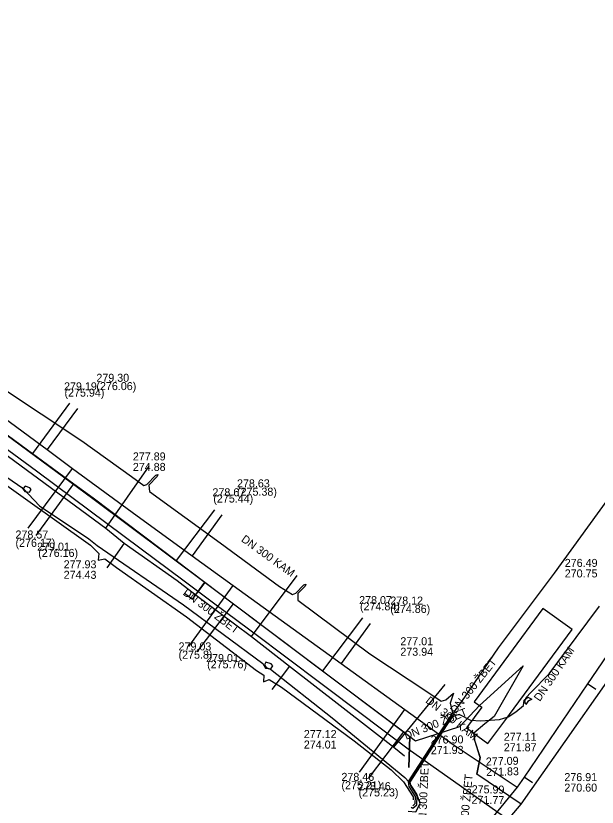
# Model space of a CAD drawing. Extents: x -598233 to -596890, y -1157848 to -1156431.
# Drawn here: x -597596.8 to -597538.8, y -1156886.7 to -1156807.7 of the extents above; entities that cross this region are included whole.
import ezdxf

# ---------------------------------------------------------------- set-up
doc = ezdxf.new("R2010")
doc.units = 0
for name, color, linetype in [('Vrstva 1', 7, 'Continuous'), ('Vrstva 13', 7, 'Continuous'), ('Vrstva 19', 7, 'Continuous'), ('Vrstva 3', 7, 'Continuous'), ('Vrstva 4', 7, 'Continuous'), ('Vrstva 42', 7, 'Continuous'), ('Vrstva 5', 7, 'Continuous'), ('Vrstva 55', 7, 'Continuous'), ('Vrstva 8', 7, 'Continuous')]:
    doc.layers.add(name, color=color, linetype=linetype)

msp = doc.modelspace()

# ---------------------------------------------------------------- linework, layer by layer
at = {"layer": 'Vrstva 1'}
for p, q in [((-597591.49, -1156846.36), (-597595.186, -1156851.395)), ((-597591.49, -1156846.36), (-597595.186, -1156851.395)), ((-597594.81, -1156859.58), (-597591.037, -1156854.44)), ((-597594.81, -1156859.58), (-597591.037, -1156854.44)), ((-597576.99, -1156857.03), (-597580.814, -1156862.105)), ((-597576.99, -1156857.03), (-597580.814, -1156862.105)), ((-597578.72, -1156871.23), (-597575.093, -1156866.416)), ((-597578.72, -1156871.23), (-597575.093, -1156866.416)), ((-597562.2, -1156867.81), (-597566.198, -1156873.117)), ((-597562.2, -1156867.81), (-597566.198, -1156873.117)), ((-597550.529, -1156876.588), (-597546.179, -1156872.61)), ((-597546.179, -1156872.61), (-597549.053, -1156877.684)), ((-597552.5, -1156878.67), (-597550.529, -1156876.588)), ((-597549.053, -1156877.684), (-597549.979, -1156878.398)), ((-597556.93, -1156880.1), (-597552.5, -1156878.67)), ((-597549.979, -1156878.398), (-597551.081, -1156879.35)), ((-597561.61, -1156883.88), (-597558.099, -1156879.219)), ((-597561.61, -1156883.88), (-597558.099, -1156879.219)), ((-597551.081, -1156879.35), (-597551.01, -1156880.04)), ((-597557.57, -1156882.78), (-597557.489, -1156879.679)), ((-597551.01, -1156880.04), (-597550.47, -1156881.78)), ((-597550.47, -1156881.78), (-597550.8, -1156883.45))]:
    msp.add_line(p, q, dxfattribs=at)
for points in [[(-597658.63, -1156810.57), (-597657.658, -1156809.853), (-597654.7, -1156807.67), (-597643.914, -1156815.601), (-597622.25, -1156831.53), (-597607.32, -1156842.489), (-597600, -1156847.9), (-597589.14, -1156855.89), (-597577.932, -1156864.277), (-597557.489, -1156879.679), (-597556.93, -1156880.1), (-597552.5, -1156878.67), (-597550.526, -1156876.585)], [(-597546.37, -1156886.45), (-597533.4, -1156867.979), (-597527.374, -1156859.341), (-597527.128, -1156858.989), (-597523.162, -1156853.304), (-597522.645, -1156852.564), (-597518.783, -1156847.028), (-597504.95, -1156827.2)], [(-597622.25, -1156831.53), (-597610.22, -1156840.36), (-597607.32, -1156842.489), (-597604.801, -1156844.337), (-597595.186, -1156851.395), (-597591.037, -1156854.44), (-597589.13, -1156855.84)], [(-597589.13, -1156855.84), (-597580.814, -1156862.105), (-597577.953, -1156864.261), (-597575.093, -1156866.416), (-597566.198, -1156873.117), (-597558.099, -1156879.219), (-597557.489, -1156879.679), (-597556.93, -1156880.1)], [(-597580, -1156865.36), (-597579.201, -1156865.962), (-597577.953, -1156864.261)], [(-597580, -1156865.36), (-597579.201, -1156865.962), (-597577.932, -1156864.277)], [(-597615.526, -1156929.546), (-597602.462, -1156924.121), (-597600, -1156923.098), (-597596.32, -1156921.57), (-597572.77, -1156912.62), (-597571.738, -1156911.986), (-597563.85, -1156907.14), (-597557.818, -1156900), (-597546.37, -1156886.45), (-597550.8, -1156883.45), (-597550.47, -1156881.78), (-597550.99, -1156880.06), (-597551.076, -1156879.353)], [(-597557.489, -1156879.679), (-597557.57, -1156882.78)]]:
    msp.add_lwpolyline(points, dxfattribs=at)
at = {"layer": 'Vrstva 13'}
msp.add_lwpolyline([(-597598.18, -1156850.63), (-597594.795, -1156853.14), (-597592.959, -1156854.503), (-597584.31, -1156860.91), (-597580.162, -1156864.021), (-597577.097, -1156866.309), (-597572.31, -1156869.884), (-597570.55, -1156871.2), (-597565.572, -1156874.953), (-597560.062, -1156879.095), (-597557.65, -1156880.92), (-597547, -1156888.42), (-597544.41, -1156893.58), (-597543.35, -1156895.58), (-597543.05, -1156896.13)], dxfattribs=at)
at = {"layer": 'Vrstva 19'}
for points in [[(-597602.54, -1156848.07), (-597587.85, -1156858.85), (-597586.01, -1156860.37), (-597580.74, -1156864.08), (-597580.43, -1156864.33), (-597578.4, -1156865.88), (-597573.29, -1156869.69), (-597569.51, -1156872.66), (-597559.1, -1156880.74), (-597558.01, -1156881.6)], [(-597587.85, -1156858.85), (-597583.52, -1156852.67)], [(-597586.01, -1156860.37), (-597587.75, -1156862.82)], [(-597573.29, -1156869.69), (-597568.74, -1156863.59)], [(-597569.51, -1156872.66), (-597571.26, -1156874.98)], [(-597559.1, -1156880.74), (-597553.95, -1156874.49)]]:
    msp.add_lwpolyline(points, dxfattribs=at)
at = {"layer": 'Vrstva 3'}
msp.add_lwpolyline([(-597544.19, -1156866.87), (-597551.05, -1156876.2), (-597550.306, -1156876.754), (-597551.83, -1156878.8), (-597549.69, -1156880.37), (-597547.99, -1156878.1), (-597541.27, -1156868.99)], close=True, dxfattribs=at)
at = {"layer": 'Vrstva 42'}
for points in [[(-597598.37, -1156844.74), (-597590.24, -1156850.14), (-597585.28, -1156853.7), (-597584.05, -1156854.6), (-597583.763, -1156854.506), (-597582.861, -1156853.574), (-597582.65, -1156853.5), (-597582.717, -1156853.713), (-597583.548, -1156854.571), (-597583.49, -1156855.2), (-597576.42, -1156860.31), (-597570.5, -1156864.69), (-597569.21, -1156865.48), (-597568.876, -1156865.343), (-597568.09, -1156864.516), (-597567.88, -1156864.44), (-597567.945, -1156864.654), (-597568.658, -1156865.403), (-597568.69, -1156866.06), (-597561.47, -1156871.4), (-597555.58, -1156875.32), (-597554.34, -1156876.13), (-597553.88, -1156876.02), (-597553.11, -1156875.33), (-597553.47, -1156876.33), (-597553.224, -1156877.297), (-597557.643, -1156884.186), (-597557.591, -1156884.675), (-597556.95, -1156885.66), (-597556.97, -1156886.4), (-597557.189, -1156886.589)], [(-597603.79, -1156850.29), (-597596.35, -1156855.59), (-597589.39, -1156860.55), (-597588.56, -1156861.4), (-597588.62, -1156862.07), (-597587.94, -1156861.92), (-597586.79, -1156862.8), (-597579.81, -1156867.72), (-597572.8, -1156873.08), (-597572.06, -1156873.54), (-597572.09, -1156874.2), (-597571.53, -1156873.97), (-597570.31, -1156874.76), (-597563.06, -1156880.12), (-597559.34, -1156883.02), (-597558.132, -1156884.209), (-597557.152, -1156885.717), (-597557.16, -1156886.015)], [(-597557.34, -1156886.72), (-597557.172, -1156886.839), (-597556.772, -1156886.494), (-597556.748, -1156885.603), (-597557.397, -1156884.606), (-597557.437, -1156884.234), (-597553.106, -1156877.484), (-597553.016, -1156877.185), (-597552, -1156875.75), (-597548.63, -1156870.82), (-597543.04, -1156863.36), (-597537.77, -1156856.09)]]:
    msp.add_lwpolyline(points, dxfattribs=at)
at = {"layer": 'Vrstva 5'}
for p, q in [((-597590.7, -1156846.89), (-597593.722, -1156851.01)), ((-597590.7, -1156846.89), (-597593.722, -1156851.01)), ((-597595.6, -1156858.87), (-597591.194, -1156852.882)), ((-597595.6, -1156858.87), (-597591.194, -1156852.882)), ((-597576.27, -1156857.53), (-597579.226, -1156861.615)), ((-597576.27, -1156857.53), (-597579.226, -1156861.615)), ((-597579.55, -1156870.67), (-597575.138, -1156864.573)), ((-597579.55, -1156870.67), (-597575.138, -1156864.573)), ((-597561.44, -1156868.37), (-597564.345, -1156872.384)), ((-597561.44, -1156868.37), (-597564.345, -1156872.384)), ((-597538.903, -1156874.979), (-597539.73, -1156874.417)), ((-597562.52, -1156883.23), (-597557.996, -1156876.978)), ((-597562.52, -1156883.23), (-597557.996, -1156876.978)), ((-597553.06, -1156880.55), (-597546.75, -1156884.75)), ((-597545.233, -1156884.297), (-597546.06, -1156883.735))]:
    msp.add_line(p, q, dxfattribs=at)
for points in [[(-597620.05, -1156831.65), (-597608.67, -1156840.023), (-597604.867, -1156842.821), (-597593.722, -1156851.01), (-597591.194, -1156852.882), (-597585.23, -1156857.27)], [(-597585.23, -1156857.27), (-597579.226, -1156861.615), (-597575.138, -1156864.573), (-597564.345, -1156872.384), (-597557.996, -1156876.978), (-597553.06, -1156880.55)], [(-597533.95, -1156865.91), (-597539.73, -1156874.417), (-597546.06, -1156883.735), (-597546.75, -1156884.75)], [(-597546.75, -1156884.75), (-597553.742, -1156893.296), (-597553.79, -1156893.355), (-597565.06, -1156907.13)]]:
    msp.add_lwpolyline(points, dxfattribs=at)
at = {"layer": 'Vrstva 55'}
for points in [[(-597598.66, -1156853.17), (-597596.25, -1156854.81), (-597595.95, -1156855.19), (-597595.47, -1156855.25), (-597595.3, -1156854.98), (-597595.44, -1156854.82), (-597595.9, -1156854.65), (-597596.1, -1156854.91), (-597595.57, -1156855.47), (-597594.49, -1156856.63), (-597589.56, -1156859.94), (-597588.73, -1156860.6), (-597580.09, -1156866.53), (-597572.18, -1156872.37), (-597571.89, -1156872.84), (-597571.36, -1156872.9), (-597571.18, -1156872.62)], [(-597556.9, -1156887.19), (-597556.47, -1156886.37), (-597556.77, -1156885.42), (-597557.57, -1156884.2), (-597557.17, -1156883.69), (-597554.002, -1156878.779), (-597553.19, -1156877.52), (-597552.53, -1156877.47), (-597551.42, -1156878.03), (-597550.38, -1156878.12), (-597548.52, -1156877.96), (-597547.654, -1156877.703), (-597546.91, -1156877.22), (-597546.134, -1156876.586), (-597546.08, -1156876.06), (-597545.7, -1156875.743), (-597545.305, -1156875.947), (-597545.71, -1156876.17), (-597545.884, -1156876.466), (-597546.004, -1156876.144), (-597545.864, -1156875.787), (-597545.39, -1156875.27), (-597543.58, -1156873.41), (-597540.885, -1156869.787), (-597538.542, -1156866.637)], [(-597571.18, -1156872.62), (-597571.35, -1156872.43), (-597571.86, -1156872.25), (-597572.02, -1156872.53), (-597571.836, -1156872.795), (-597571.42, -1156872.95), (-597565.23, -1156877.82), (-597558, -1156883.76)], [(-597557.643, -1156887.128), (-597556.9, -1156887.19), (-597556.47, -1156886.37), (-597556.77, -1156885.42), (-597557.57, -1156884.2), (-597558, -1156883.76)]]:
    msp.add_lwpolyline(points, dxfattribs=at)

# ---------------------------------------------------------------- texts
at = {"layer": 'Vrstva 4'}
for s, p in [('279.19', (-597592.029, -1156845.091)), ('(275.94)', (-597591.982, -1156845.716)), ('278.67', (-597577.202, -1156855.673)), ('(275.44)', (-597577.115, -1156856.298)), ('279.01', (-597594.716, -1156861.107)), ('(276.16)', (-597594.611, -1156861.732)), ('277.93', (-597592.067, -1156862.871)), ('274.43', (-597592.067, -1156863.921)), ('278.07', (-597562.55, -1156866.445)), ('(274.84)', (-597562.465, -1156867.07)), ('277.01', (-597558.434, -1156870.557)), ('273.94', (-597558.434, -1156871.607)), ('279.01', (-597577.836, -1156872.235)), ('(275.76)', (-597577.736, -1156872.86)), ('277.12', (-597568.074, -1156879.829)), ('277.11', (-597548.101, -1156880.104)), ('274.01', (-597568.074, -1156880.879)), ('271.87', (-597548.101, -1156881.154)), ('278.46', (-597562.669, -1156885.039)), ('(275.23)', (-597562.606, -1156885.664))]:
    msp.add_text(s, height=0.8, dxfattribs=at).set_placement(p)
for s, height, rotation, p in [('DN 300 ŽBET', 0.8, 323.00504, (-597580.22, -1156865.452)), ('DN 300 ŽBET', 0.8, 51.42578, (-597552.911, -1156877.46)), ('DN 300 ŽBET', 0.79999, 21.77042, (-597557.859, -1156880.01)), ('276.90', 0.8, 0.69948, (-597555.4, -1156880.4)), ('271.93', 0.8, 0.69948, (-597555.387, -1156881.45)), ('277.09', 0.8, 1.61535, (-597549.883, -1156882.58)), ('DN 300 ŽBET', 0.79999, 87.40036, (-597555.884, -1156888.842)), ('271.83', 0.8, 1.61535, (-597549.853, -1156883.63)), ('DN 300 ŽBET', 0.8, 84.29578, (-597551.856, -1156890.115)), ('275.99', 0.8, 359.28304, (-597551.312, -1156885.341)), ('271.77', 0.8, 359.28304, (-597551.325, -1156886.391))]:
    msp.add_text(s, height=height, rotation=rotation, dxfattribs=at).set_placement(p)
at = {"layer": 'Vrstva 8'}
for s, p in [('279.30', (-597588.798, -1156844.233)), ('(276.06)', (-597588.798, -1156845.065)), ('277.89', (-597585.154, -1156852.09)), ('274.88', (-597585.154, -1156853.14)), ('278.63', (-597574.75, -1156854.783)), ('(275.38)', (-597574.75, -1156855.615)), ('278.57', (-597596.88, -1156859.893)), ('(276.17)', (-597596.88, -1156860.725)), ('276.49', (-597542.009, -1156862.731)), ('270.75', (-597542.009, -1156863.781)), ('278.12', (-597559.435, -1156866.495)), ('(274.86)', (-597559.435, -1156867.327)), ('279.03', (-597580.59, -1156871.07)), ('(275.8)', (-597580.59, -1156871.902)), ('278.46', (-597564.318, -1156884.109)), ('276.91', (-597542.049, -1156884.131)), ('(275.21)', (-597564.318, -1156884.941)), ('270.60', (-597542.049, -1156885.181))]:
    msp.add_text(s, height=0.8, dxfattribs=at).set_placement(p)
for rotation, p in [(324.10841, (-597574.399, -1156860.119)), (55.8076, (-597544.501, -1156876.231)), (321.30879, (-597555.98, -1156876.215))]:
    msp.add_text('DN 300 KAM', height=0.8, rotation=rotation, dxfattribs=at).set_placement(p)

doc.saveas('drawing.dxf')
